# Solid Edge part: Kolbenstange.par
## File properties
Last saved by: bmolnar
Revision: 77
Dokumentum tartalom típus: 0
Sűrűség: 0,000 kg/m^3
Pontosság: 0,990
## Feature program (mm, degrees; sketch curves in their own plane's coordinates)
base feature "unnamed BaseFeature 1"
sketch for "unnamed Protrusion 1" plane through (42.5, 0, 0) normal (1, 0, 0) x-axis (0, 0, -1)
  circle centre (0, 0) radius 31.5
extrude "unnamed Protrusion 1" add finite 17.85 along +normal
sketch for "Kihúzás_4" #1 plane through (42.5, 0, 0) normal (1, 0, 0) x-axis (0, 0, -1)
  circle centre (0, 0) radius 8
sketch for "Kihúzás_4" #2 plane through (42.5, 0, 0) normal (1, 0, 0) x-axis (0, 0, -1)
  circle centre (0, 0) radius 31.5
extrude "Kihúzás_4" add finite 10.85 along -normal
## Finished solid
Body 1: solid body, 14 faces, 20 edges, 13 vertices.
  Faces by surface: plane 8, cylinder 4, cone 1, torus 1
  Edges by curve: circle 10, line 6, curve on surface 2, ellipse 2
Bounding box of the edges (mm; curved faces can reach further): 60.350 x 63.000 x 63.000, from (0, -31.5, -31.5) to (60.35, 31.5, 31.5).
Cylindrical faces by radius (mm): R3.3235 x1, R4.125 x1, R8 x1, R31.5 x1
Conical faces (half-angle, radius in mm at the cone's reference point): 59 deg R1.6618 x1
Toroidal faces (ring radius, tube radius in mm): R6.2 r1.8 x1
Planar faces by outward normal: +x 1, +y 1, -x 3, -y 1, oblique 2
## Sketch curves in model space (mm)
circle centre (42.5, 0, 0) radius 31.5
circle centre (42.5, 0, 0) radius 8
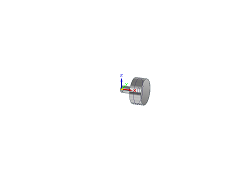
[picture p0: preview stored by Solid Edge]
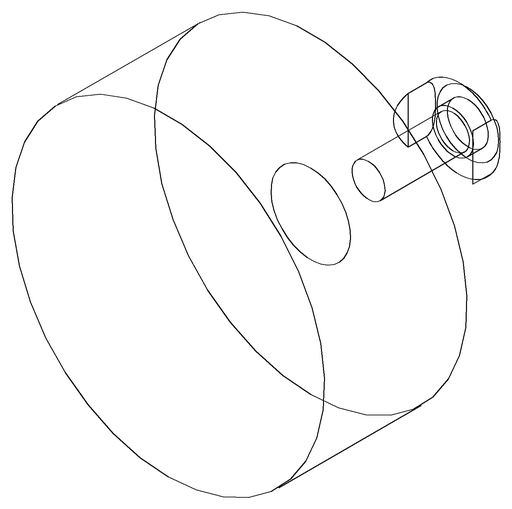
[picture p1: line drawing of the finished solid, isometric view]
